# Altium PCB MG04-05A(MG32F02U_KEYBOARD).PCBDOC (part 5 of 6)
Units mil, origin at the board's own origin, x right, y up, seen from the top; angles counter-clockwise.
Board outline 17912.8 x 10422.68 mil, 2 copper layers (Top Layer, Bottom Layer); 623 components, 347 nets, 1816 pads, 821 vias.
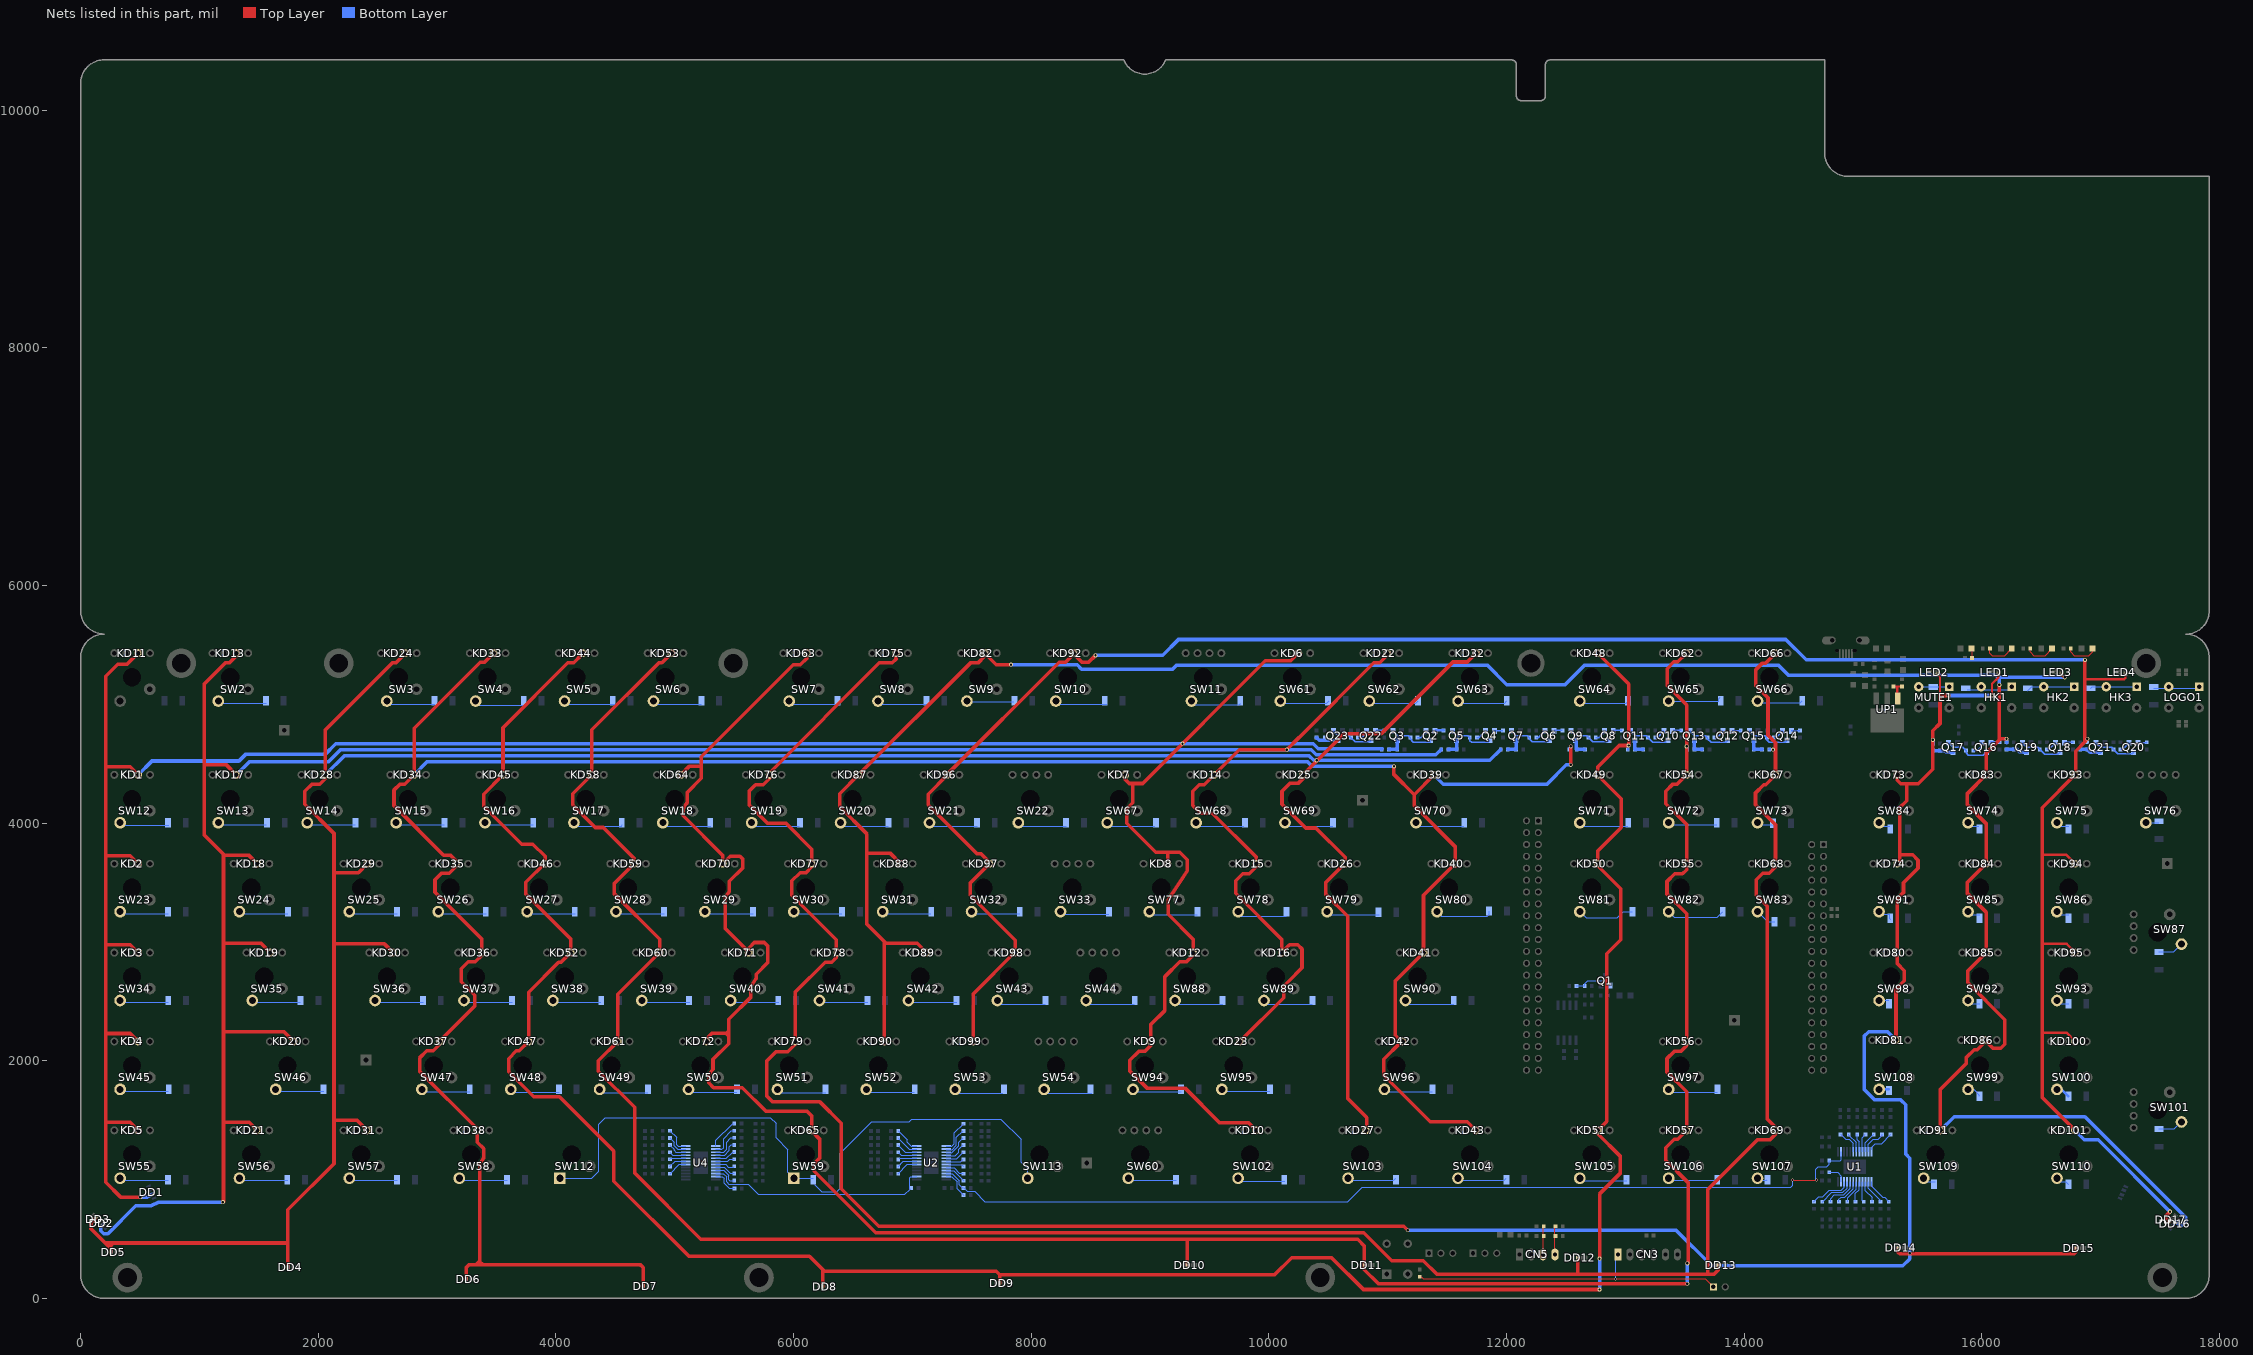
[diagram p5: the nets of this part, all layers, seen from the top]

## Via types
v1: diameter 30, hole 12, Top Layer to Bottom Layer, tented both sides, 273 vias
v2: diameter 26, hole 16, Top Layer to Bottom Layer, tented both sides, 181 vias
v3: diameter 26, hole 12, Top Layer to Bottom Layer, tented both sides, 165 vias
v4: diameter 33, hole 20, Top Layer to Bottom Layer, tented both sides, 61 vias
v5: diameter 25, hole 12, Top Layer to Bottom Layer, tented both sides, 47 vias
v6: diameter 20, hole 12, Top Layer to Bottom Layer, tented both sides, 40 vias
v7: diameter 30, hole 16, Top Layer to Bottom Layer, tented both sides, 30 vias
v8: diameter 28, hole 16, Top Layer to Bottom Layer, tented both sides, 12 vias
v9: diameter 35, hole 20, Top Layer to Bottom Layer, tented both sides, 5 vias
v10: diameter 25, hole 16, Top Layer to Bottom Layer, tented both sides, 3 vias
v11: diameter 40, hole 12, Top Layer to Bottom Layer, tented both sides, 3 vias
v12: diameter 40, hole 20, Top Layer to Bottom Layer, tented both sides, 1 vias

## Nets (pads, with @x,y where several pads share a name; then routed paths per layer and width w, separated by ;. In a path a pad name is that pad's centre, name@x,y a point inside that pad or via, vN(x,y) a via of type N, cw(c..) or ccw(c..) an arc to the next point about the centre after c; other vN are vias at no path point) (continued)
NetD5_1: D5.1 SW2.1 | length 400
  Bottom Layer w8: SW2.1@1163.15,5010 D5.1@1563.15,5010
NetD6_1: D6.1 SW3.1 | length 375.1
  Bottom Layer w8: SW3.1@2603.27,5000 D6.1@2978.35,5000
NetD7_1: D7.1 SW4.1 | length 378.3
  Bottom Layer w8: SW4.1@3350.04,4993.11 D7.1@3728.35,4993.11
NetD8_1: D8.1 SW5.1 | length 400.1
  Bottom Layer w8: SW5.1@4099.27,5000 D8.1@4499.37,5000
NetD9_1: D9.1 SW6.1 | length 375.9
  Bottom Layer w8: SW6.1@4847.27,5000 D9.1@5223.15,5000
NetD10_1: D10.1 SW7.1 | length 400.1
  Bottom Layer w8: SW7.1@5989.28,5000 D10.1@6389.37,5000
NetD11_1: D11.1 SW8.1 | length 400.1
  Bottom Layer w8: SW8.1@6736.94,5000 D11.1@7137.04,5000
NetD12_1: D12.1 SW9.1 | length 393.9
  Bottom Layer w8: SW9.1@7458.13,5020 D12.1@7852,5020
NetD13_1: D13.1 SW10.1 | length 400.1
  Bottom Layer w8: SW10.1@8233.05,5000 D13.1@8633.15,5000
NetD14_1: D14.1 SW11.1 | length 435.2
  Bottom Layer w8: SW11.1@9347.98,5026.89 9359.05,5015.81 9359.05,5007.73 9370.31,4996.47 9749,4996.47 9758.35,5005.81 D14.1@9762,5005.81
NetD15_1: D15.1 SW12.1 | length 403.1
  Bottom Layer w8: SW12.1@336.9,3980 D15.1@740,3980
NetD16_1: D16.1 SW13.1 | length 400
  Bottom Layer w8: SW13.1@1163.74,3986.4 D16.1@1563.74,3986.4
NetD17_1: D17.1 SW14.1 | length 400
  Bottom Layer w8: SW14.1@1911.62,3986.4 D17.1@2311.62,3986.4
NetD18_1: D18.1 SW15.1 | length 400
  Bottom Layer w8: SW15.1@2659.73,3986.4 D18.1@3059.73,3986.4
NetD19_1: D19.1 SW16.1 | length 400
  Bottom Layer w8: SW16.1@3407.73,3986.4 D19.1@3807.73,3986.4
NetD20_1: D20.1 SW17.1 | length 412.6
  Bottom Layer w8: SW17.1@4155.76,3971.4 4553.15,3971.4 D20.1@4555.76,3986.4
NetD21_1: D21.1 SW18.1 | length 397.4
  Bottom Layer w8: SW18.1@4903.75,3971.4 D21.1@5301.14,3971.4
NetD22_1: D22.1 SW19.1 | length 397.4
  Bottom Layer w8: SW19.1@5651.78,3971.4 D22.1@6049.17,3971.4
NetD23_1: D23.1 SW20.1 | length 397.4
  Bottom Layer w8: SW20.1@6399.82,3971.4 D23.1@6797.22,3971.4
NetD24_1: D24.1 SW21.1 | length 397.4
  Bottom Layer w8: SW21.1@7147.9,3971.4 D24.1@7545.29,3971.4
NetD25_1: D25.1 SW22.1 | length 397.4
  Bottom Layer w8: SW22.1@7895.89,3971.4 D25.1@8293.28,3971.4
NetD26_1: D26.1 SW23.1 | length 400
  Bottom Layer w8: SW23.1@336.85,3238 D26.1@736.85,3238
NetD27_1: D27.1 SW24.1 | length 400
  Bottom Layer w8: SW24.1@1340.79,3238 D27.1@1740.79,3238
NetD28_1: D28.1 SW25.1 | length 400
  Bottom Layer w8: SW25.1@2266.18,3238 D28.1@2666.18,3238
NetD29_1: D29.1 SW26.1 | length 400
  Bottom Layer w8: SW26.1@3014.06,3238 D29.1@3414.06,3238
NetD30_1: D30.1 SW27.1 | length 400
  Bottom Layer w8: SW27.1@3762.1,3238 D30.1@4162.1,3238
NetD31_1: D31.1 SW28.1 | length 400
  Bottom Layer w8: SW28.1@4510.09,3238 D31.1@4910.09,3238
NetD32_1: D32.1 SW29.1 | length 400
  Bottom Layer w8: SW29.1@5258.16,3238 D32.1@5658.16,3238
NetD33_1: D33.1 SW30.1 | length 400
  Bottom Layer w8: SW30.1@6006.15,3238 D33.1@6406.15,3238
NetD34_1: D34.1 SW31.1 | length 400
  Bottom Layer w8: SW31.1@6754.22,3238 D34.1@7154.22,3238
NetD35_1: D35.1 SW32.1 | length 400
  Bottom Layer w8: SW32.1@7502.27,3238 D35.1@7902.27,3238
NetD36_1: D36.1 SW33.1 | length 400
  Bottom Layer w8: SW33.1@8250.3,3233 D36.1@8650.3,3233
NetD37_1: D37.1 SW34.1 | length 400
  Bottom Layer w8: SW34.1@336.85,2490.4 D37.1@736.85,2490.4
NetD38_1: D38.1 SW35.1 | length 400
  Bottom Layer w8: SW35.1@1449.06,2490.4 D38.1@1849.06,2490.4
NetD39_1: D39.1 SW36.1 | length 400
  Bottom Layer w8: SW36.1@2482.52,2490.4 D39.1@2882.52,2490.4
NetD40_1: D40.1 SW37.1 | length 400
  Bottom Layer w8: SW37.1@3230.6,2490.4 D40.1@3630.6,2490.4
NetD41_1: D41.1 SW38.1 | length 400
  Bottom Layer w8: SW38.1@3978.63,2490.4 D41.1@4378.63,2490.4
NetD42_1: D42.1 SW39.1 | length 400
  Bottom Layer w8: SW39.1@4726.67,2490.4 D42.1@5126.67,2490.4
NetD43_1: D43.1 SW40.1 | length 400
  Bottom Layer w8: SW40.1@5474.7,2490.4 D43.1@5874.7,2490.4
NetD44_1: D44.1 SW41.1 | length 400
  Bottom Layer w8: SW41.1@6222.73,2490.4 D44.1@6622.73,2490.4
NetD45_1: D45.1 SW42.1 | length 400
  Bottom Layer w8: SW42.1@6970.76,2490.4 D45.1@7370.76,2490.4
NetD46_1: D46.1 SW43.1 | length 400
  Bottom Layer w8: SW43.1@7718.8,2475.4 D46.1@8118.8,2475.4
NetD47_1: D47.1 SW44.1 | length 400
  Bottom Layer w8: SW44.1@8466.79,2475.4 D47.1@8866.79,2475.4
NetD48_1: D48.1 SW45.1 | length 400
  Bottom Layer w8: SW45.1@336.85,1742.3 D48.1@736.85,1742.3
NetD49_1: D49.1 SW46.1 | length 400
  Bottom Layer w8: SW46.1@1645.91,1742.3 D49.1@2045.91,1742.3
NetD50_1: D50.1 SW47.1 | length 398
  Bottom Layer w8: SW47.1@2876.23,1737.3 D50.1@3274.28,1737.3
NetD51_1: D51.1 SW48.1 | length 400
  Bottom Layer w8: SW48.1@3627.02,1735 D51.1@4027,1735
NetD52_1: D52.1 SW49.1 | length 400
  Bottom Layer w8: SW49.1@4372,1730 D52.1@4772,1730
NetD53_1: D53.1 SW50.1 | length 400
  Bottom Layer w8: SW50.1@5122,1735 D53.1@5522,1735
NetD54_1: D54.1 SW51.1 | length 400
  Bottom Layer w8: SW51.1@5868.37,1732.3 D54.1@6268.37,1732.3
NetD55_1: D55.1 SW52.1 | length 400
  Bottom Layer w8: SW52.1@6617,1735 D55.1@7017,1735
NetD56_1: D56.1 SW53.1 | length 400
  Bottom Layer w8: SW53.1@7359.44,1727.3 D56.1@7759.44,1727.3
NetD57_1: D57.1 SW54.1 | length 396.6
  Bottom Layer w8: SW54.1@8112.48,1727.3 D57.1@8509.08,1727.3
NetD58_1: D58.1 SW55.1 | length 400
  Bottom Layer w8: SW55.1@336.85,994.3 D58.1@736.85,994.3
NetD59_1: D59.1 SW56.1 | length 400
  Bottom Layer w8: SW56.1@1340.8,994.3 D59.1@1740.8,994.3
NetD60_1: D60.1 SW57.1 | length 400
  Bottom Layer w8: SW57.1@2266,994.3 D60.1@2666,994.3
NetD61_1: D61.1 SW58.1 | length 400
  Bottom Layer w8: SW58.1@3191.21,994.3 D61.1@3591.21,994.3
NetD62_1: D62.1 SW59.1 SW112.1 SW113.1 | length 5585.9
  Bottom Layer w8: SW112.1@4032.9,1011.19 4302.34,1011.19 4361.85,1070.7 4361.85,1465.7 4416.68,1520.53 5804.89,1520.53 5852.69,1472.72 5852.69,1350.77 5952,1251.47 5952,1060.6 SW59.1@6001.41,1011.19 D62.1@6164.63,1011.19 ; D62.1@6171.85,960.7 6236.85,895.7 6361.23,895.7 6393.21,927.68 6393.21,1222.06 6656.41,1485.25 6971.41,1485.25 6995.64,1509.48 7743.98,1509.48 7915.64,1337.83 7915.64,1147.83 7969.91,1093.55 SW113.1@7969.91,1011.19
NetD63_1: D63.1 SW60.1 | length 400
  Bottom Layer w8: SW60.1@8821.14,994.3 D63.1@9221.14,994.3
NetD64_1: D64.1 SW61.1 | length 425.6
  Bottom Layer w8: SW61.1@10095.89,5026.89 10112.78,5010 10486.26,5010 D64.1@10506.26,5030
NetD65_1: D65.1 SW62.1 | length 425.6
  Bottom Layer w8: SW62.1@10844.08,5026.89 10860.97,5010 11234.45,5010 D65.1@11254.45,5030
NetD66_1: D66.1 SW63.1 | length 425.6
  Bottom Layer w8: SW63.1@11592,5026.89 11608.89,5010 11982.37,5010 D66.1@12002.37,5030
NetD67_1: D67.1 SW64.1 | length 425.6
  Bottom Layer w8: SW64.1@12615.74,5026.89 12632.62,5010 13006.11,5010 D67.1@13026.11,5030
NetD68_1: D68.1 SW65.1 | length 460.2
  Bottom Layer w8: SW65.1@13363.65,5026.89 13785.35,5026.89 13785.35,5047 D68.1@13798.35,5060
NetD69_1: D69.1 SW66.1 | length 383.1
  Bottom Layer w8: SW66.1@14113.15,5011 14469.35,5011 D69.1@14488.35,5030
NetD70_1: D70.1 HK1.1 HK1.3 | length 378.6
  Bottom Layer w8: D70.1@15875.41,5123.48 HK1.3@15994,5123.48 ; HK1.3@15993.6,5123.48 HK1.3@15994,5123.48 ; HK1.1@16249.6,5123.48 HK1.3@15994,5123.48 ; HK1.1@16250,5147 HK1.1@16254,5147
NetD71_1: D71.1 HK2.1 HK2.3 | length 402.3
  Bottom Layer w8: D71.1@16387,5114.8 16419.2,5147 HK2.3@16520,5147 HK2.1@16776,5147
NetD72_1: D72.1 HK3.1 HK3.3 | length 390.1
  Bottom Layer w8: D72.1@16917,5134.8 16929.2,5147 HK3.3@17046,5147 HK3.1@17302,5147
NetD73_1: D73.1 SW67.1 | length 400
  Bottom Layer w8: SW67.1@8638.15,3975 D73.1@9038.15,3975
NetD74_1: D74.1 SW68.1 | length 397.4
  Bottom Layer w8: SW68.1@9392.03,3971.4 D74.1@9789.42,3971.4
NetD75_1: D75.1 SW69.1 | length 397.4
  Bottom Layer w8: SW69.1@10140.02,3971.4 D75.1@10537.42,3971.4
NetD76_1: D76.1 SW70.1 | length 397.4
  Bottom Layer w8: SW70.1@11242.47,3971.4 D76.1@11639.86,3971.4
NetD77_1: D77.1 SW71.1 | length 397.4
  Bottom Layer w8: SW71.1@12620.35,3971.4 D77.1@13017.74,3971.4
NetD78_1: D78.1 SW72.1 | length 400
  Bottom Layer w8: SW72.1@13368.42,3986.4 D78.1@13768.42,3986.4
NetD79_1: D79.1 SW73.1 | length 125.7
  Bottom Layer w8: SW73.1@14116.45,3986.4 D79.1@14242.2,3986.4
NetD80_1: D80.1 MUTE1.1 MUTE1.3 | length 256
  Bottom Layer w8: MUTE1.3@15468,5147 MUTE1.1@15724,5147
NetD81_1: D81.1 SW74.1 | length 101.3
  Bottom Layer w8: SW74.1@15883.52,4003.29 15911.81,3975 D81.1@15973.15,3975
NetD82_1: D82.1 SW75.1 | length 98.7
  Bottom Layer w8: SW75.1@16631.35,3975 D82.1@16730.09,3975
NetD83_1: D83.1 SW76.1 | length 98.7
  Bottom Layer w8: SW76.1@17389.6,4001.25 D83.1@17488.34,4001.25
NetD84_1: D84.1 SW77.1 | length 400
  Bottom Layer w8: SW77.1@8998.33,3228 D84.1@9398.33,3228
NetD85_1: D85.1 SW78.1 | length 400
  Bottom Layer w8: SW78.1@9746.36,3218 D85.1@10146.36,3218
NetD86_1: D86.1 SW79.1 | length 437.6
  Bottom Layer w8: SW79.1@10489.39,3228 D86.1@10927,3228
NetD87_1: D87.1 SW80.1 | length 486.7
  Bottom Layer w8: SW80.1@11414.79,3254.89 11451.68,3218 11838.53,3218 11852.2,3231.66 D87.1@11852.2,3260
NetD88_1: D88.1 SW81.1 | length 486.6
  Bottom Layer w8: SW81.1@12615.58,3254.89 12668.47,3202 12929.15,3202 12982.04,3254.89 D88.1@13058.35,3254.89
NetD89_1: D89.1 SW82.1 | length 492.7
  Bottom Layer w8: SW82.1@13363.65,3254.89 13409.54,3209 13772.46,3209 D89.1@13818.35,3254.89
NetD90_1: D90.1 SW83.1 | length 178.8
  Bottom Layer w8: SW83.1@14111.65,3254.89 14196.65,3169.89 D90.1@14255.2,3169.89
NetD91_1: D91.1 SW84.1 | length 67.9
  Bottom Layer w8: SW84.1@15155.26,3975 D91.1@15223.15,3975
NetD92_1: D92.1 SW85.1 | length 98.7
  Bottom Layer w8: SW85.1@15883.34,3226.6 D92.1@15982.09,3226.6
NetD93_1: D93.1 SW86.1 | length 98.7
  Bottom Layer w8: SW86.1@16630.57,3226.6 D93.1@16729.31,3226.6
NetD94_1: D94.1 SW87.1 | length 217
  Bottom Layer w8: D94.1@17489.6,2916.05 17614.4,2916.05 SW87.1@17679.6,2981.25
NetD95_1: D95.1 SW88.1 | length 395.6
  Bottom Layer w8: SW88.1@9214.87,2475.4 D95.1@9610.43,2475.4
NetD96_1: D96.1 SW89.1 | length 400
  Bottom Layer w8: SW89.1@9962.9,2475.4 D96.1@10362.9,2475.4
NetD97_1: D97.1 SW90.1 | length 400
  Bottom Layer w8: SW90.1@11153.85,2475.4 D97.1@11553.85,2475.4
NetD98_1: D98.1 SW91.1 | length 155
  Bottom Layer w8: SW91.1@15123.24,3260.95 15151.38,3232.8 15224.28,3232.8 15224.28,3195.94 D98.1@15228.09,3192.13
NetD99_1: D99.1 SW92.1 | length 98.7
  Bottom Layer w8: SW92.1@15883.52,2479 D99.1@15982.27,2479
NetD100_1: D100.1 SW93.1 | length 98.7
  Bottom Layer w8: SW93.1@16631.57,2479 D100.1@16730.31,2479
NetD101_1: D101.1 SW94.1 | length 403.3
  Bottom Layer w8: SW94.1@8859.08,1737.29 D101.1@9262.42,1737.29
NetD102_1: D102.1 SW95.1 | length 400
  Bottom Layer w8: SW95.1@9608.54,1742.3 D102.1@10008.54,1742.3
NetD103_1: D103.1 SW96.1 | length 412.2
  Bottom Layer w8: SW96.1@10971.89,1759.19 10993.34,1737.74 D103.1@11375.23,1737.74
NetD104_1: D104.1 SW97.1 | length 414.6
  Bottom Layer w8: SW97.1@13362.5,1740 13363.65,1735 D104.1@13773.15,1735
NetD105_1: D105.1 SW98.1 | length 81.9
  Bottom Layer w8: SW98.1@15134.84,2507.29 D105.1@15216.77,2507.29
NetD106_1: D106.1 SW99.1 | length 125.3
  Bottom Layer w8: SW99.1@15883.5,1759.19 15929.28,1759.19 15978.35,1710.12 D106.1@15978.35,1700
NetD107_1: D107.1 SW100.1 | length 121.5
  Bottom Layer w20: SW100.1@16631.36,1759.19 16669.16,1759.19 D107.1@16728.35,1700
NetD108_1: D108.1 SW101.1 | length 214.4
  Bottom Layer w8: D108.1@17489.6,1426.05 17620.46,1426.05 SW101.1@17679.5,1485.09
NetD109_1: D109.1 SW102.1 | length 372
  Bottom Layer w8: SW102.1@9759.15,986 D109.1@10131.15,986
NetD110_1: D110.1 SW103.1 | length 404.8
  Bottom Layer w8: SW103.1@10670.54,994.3 11051.45,994.3 D110.1@11068.35,1011.2
NetD111_1: D111.1 SW104.1 | length 421.4
  Bottom Layer w8: SW104.1@11590.98,1011.19 11607.87,994.3 11981.45,994.3 D111.1@11998.35,1011.2
NetD112_1: D112.1 SW105.1 | length 392.8
  Bottom Layer w8: SW105.1@12617,990 D112.1@13009.75,990
NetD113_1: D113.1 SW106.1 | length 423.5
  Bottom Layer w8: SW106.1@13363.65,1011.19 13380.54,994.3 13756.25,994.3 D113.1@13773.15,1011.2
NetD114_1: D114.1 SW107.1 | length 81.1
  Bottom Layer w8: SW107.1@14116.43,994.3 14189.61,994.3 D114.1@14195.2,999.89
NetD115_1: D115.1 SW108.1 | length 82.9
  Bottom Layer w20: SW108.1@15135.47,1759.19 D115.1@15218.35,1759.19
NetD116_1: D116.1 SW109.1 | length 98.7
  Bottom Layer w8: SW109.1@15509.49,982.9 D116.1@15608.24,982.9
NetD117_1: D117.1 SW110.1 | length 106.3
  Bottom Layer w8: SW110.1@16631.54,982.9 16705.45,982.9 D117.1@16728.35,960
NetD118_1: D118.1 LOGO1.1 LOGO1.3 | length 368.8
  Bottom Layer w8: D118.1@17447,5134.8 LOGO1.1@17815.8,5134.8
NetD119_2: D119.2 R90.1 | length 91
  Top Layer w8: D119.2@15911,5460 D119.2@15917,5454 ; D119.2@15911,5470 15917,5464 D119.2@15917,5454 ; R90.1@15917,5390 D119.2@15917,5454
NetD120_2: D120.2 R99.1 | length 257.1
  Top Layer w10: R99.1@16067,5470 16067,5430 16087,5410 16191,5410 D120.2@16251,5470
NetD121_2: D121.2 R107.1 | length 251.3
  Top Layer w8: R107.1@16407,5470 16407,5440 16437,5410 16531,5410 D121.2@16591,5470
NetD122_2: D122.2 R108.1 | length 268.9
  Top Layer w8: R108.1@16747,5470 16747,5440 16777,5410 16901,5410 16931,5440 D122.2@16931,5470
NetQ1_1: Q1.1 R2.2 R3.1 | length 329.1
  Bottom Layer w8: R2.2@12587,2630 R3.1@12657,2630 12657,2649.59 12681.41,2674 12828.4,2674 Q1.1@12869.4,2633
NetQ2_1: Q2.1 R6.2 | length 91.7
  Bottom Layer w12: R6.2@11250,4720 11276.6,4720 Q2.1@11322.6,4766
NetQ2_2: Q2.2 R8.2 | length 68.6
  Bottom Layer w20: Q2.2@11401.4,4780 R8.2@11470,4780
NetQ2_3: Q2.3 Q3.1 R7.2 | length 363.4
  Bottom Layer w12: Q3.1@11042.6,4776 11082.1,4736.5 11173.5,4736.5 R7.2@11190,4720 11190,4708 11216,4682 Q2.3@11360,4682
NetQ3_3: Q3.3 R9.2 R10.1 | length 147.3
  Bottom Layer w30: R10.1@11010,4620 R9.2@11080,4620 Q3.3@11080,4697.26
NetQ4_1: Q4.1 R11.2 | length 95.8
  Bottom Layer w12: R11.2@11750,4720 11766.6,4720 Q4.1@11822.6,4776
NetQ4_2: Q4.2 R13.2 | length 68.6
  Bottom Layer w12: Q4.2@11897.4,4776 R13.2@11966,4776
NetQ4_3: Q4.3 Q5.1 R12.2 | length 379
  Bottom Layer w12: Q5.1@11542.6,4776 11582.1,4736.5 11673.5,4736.5 R12.2@11690,4720 11690,4695 11705,4680 11842.74,4680 Q4.3@11860,4697.26
NetQ5_3: Q5.3 R14.2 R15.1 | length 147.3
  Bottom Layer w30: R15.1@11510,4620 R14.2@11580,4620 Q5.3@11580,4697.26
NetQ6_1: Q6.1 R16.2 | length 95.8
  Bottom Layer w12: R16.2@12250,4720 12266.6,4720 Q6.1@12322.6,4776
NetQ6_2: Q6.2 R18.2 | length 68.6
  Bottom Layer w12: Q6.2@12401.4,4780 R18.2@12470,4780
NetQ6_3: Q6.3 Q7.1 R17.2 | length 366
  Bottom Layer w12: Q7.1@12042.6,4776 12082.1,4736.5 12173.5,4736.5 R17.2@12190,4720 12190,4710 12215,4685 12347.74,4685 Q6.3@12360,4697.26
NetQ7_3: Q7.3 R19.2 R20.1 | length 147.3
  Bottom Layer w30: R20.1@12010,4620 R19.2@12080,4620 Q7.3@12080,4697.26
NetQ8_1: Q8.1 R21.2 | length 101.7
  Bottom Layer w12: R21.2@12750,4720 12776.6,4720 12822.6,4766 Q8.1@12822.6,4776
NetQ8_2: Q8.2 R23.2 | length 72.6
  Bottom Layer w12: Q8.2@12897.4,4780 R23.2@12970,4780
NetQ8_3: Q8.3 Q9.1 R22.2 | length 360.2
  Bottom Layer w12: Q9.1@12542.6,4776 12582.1,4736.5 12673.5,4736.5 R22.2@12690,4720 12725,4685 12847.74,4685 Q8.3@12860,4697.26
NetQ9_3: Q9.3 R24.2 R25.1 | length 137.2
  Bottom Layer w30: R25.1@12587,4621.4 Q9.3@12587,4690 ; R25.1@12590,4620 R24.2@12658.6,4620
NetQ10_1: Q10.1 R26.2 | length 95.8
  Bottom Layer w12: R26.2@13250,4720 13266.6,4720 Q10.1@13322.6,4776
NetQ10_2: Q10.2 R28.2 | length 68.6
  Bottom Layer w12: Q10.2@13401.4,4780 R28.2@13470,4780
NetQ10_3: Q10.3 Q11.1 R27.2 | length 364.9
  Bottom Layer w12: Q11.1@13042.6,4776 13082.1,4736.5 13173.5,4736.5 R27.2@13190,4720 13230,4680 13240,4680 ; 13265,4680 13240,4680 ; Q10.3@13342.74,4680 13240,4680
NetQ11_3: Q11.3 R29.2 R30.1 | length 147.3
  Bottom Layer w30: Q11.3@13080,4697.26 R30.1@13080,4620 R29.2@13150,4620
NetQ12_1: Q12.1 R31.2 | length 95.8
  Bottom Layer w12: R31.2@13750,4720 13766.6,4720 Q12.1@13822.6,4776
NetQ12_2: Q12.2 R33.2 | length 74.3
  Bottom Layer w12: Q12.2@13897.4,4776 13966,4776 R33.2@13970,4780
NetQ12_3: Q12.3 Q13.1 R32.2 | length 373.3
  Bottom Layer w12: Q13.1@13542.6,4776 13582.1,4736.5 13673.5,4736.5 R32.2@13690,4720 13690,4710 13720,4680 13845.87,4680 13861.56,4695.7 Q12.3@13860,4697.26
NetQ13_3: Q13.3 R34.2 R35.1 | length 145.9
  Bottom Layer w12: R34.2@13646.6,4620 R34.2@13648.6,4620
  Bottom Layer w30: Q13.3@13580,4697.26 R35.1@13580,4620 R34.2@13646.6,4620
NetQ14_1: Q14.1 R36.2 | length 95.8
  Bottom Layer w12: R36.2@14250,4720 14266.6,4720 Q14.1@14322.6,4776
NetQ14_2: Q14.2 R38.2 | length 68.6
  Bottom Layer w12: Q14.2@14397.4,4776 R38.2@14466,4776
NetQ14_3: Q14.3 Q15.1 R37.2 | length 376
  Bottom Layer w12: Q15.1@14042.6,4776 14082.1,4736.5 14173.5,4736.5 R37.2@14190,4720 14190,4700 14210,4680 14342.74,4680 Q14.3@14360,4697.26
NetQ15_3: Q15.3 R39.2 R40.1 | length 147.3
  Bottom Layer w30: Q15.3@14080,4697.26 R39.2@14080,4620 R40.1@14150,4620
NetQ16_1: Q16.1 R41.2 | length 116
  Bottom Layer w12: R41.2@15927,4610 15961,4610 15989,4638 15989,4665.4 Q16.1@15999.6,4676
NetQ16_2: Q16.2 R43.2 | length 68.6
  Bottom Layer w20: Q16.2@16078.4,4680 R43.2@16147,4680
NetQ16_3: Q16.3 Q17.1 R42.2 | length 382.1
  Bottom Layer w12: Q17.1@15719.6,4676 15759.1,4636.5 15840.5,4636.5 R42.2@15867,4610 15867,4591 15886,4572 16011.74,4572 Q16.3@16037,4597.26
NetQ17_3: Q17.3 R44.2 R45.1 | length 175.3
  Bottom Layer w30: R45.1@15587,4610 15687.55,4610 15700.29,4597.26 Q17.3@15757,4597.26
NetQ18_1: Q18.1 R46.2 | length 95.8
  Bottom Layer w12: R46.2@16547,4620 16563.6,4620 Q18.1@16619.6,4676
NetQ18_2: Q18.2 R48.2 | length 74.3
  Bottom Layer w12: Q18.2@16694.4,4676 16698.4,4680 R48.2@16767,4680
NetQ18_3: Q18.3 Q19.1 R47.2 | length 364.3
  Bottom Layer w12: Q19.1@16339.6,4676 16379.1,4636.5 16470.5,4636.5 R47.2@16487,4620 16527,4580 16639.74,4580 Q18.3@16657,4597.26
NetQ19_3: Q19.3 R49.2 R50.1 | length 179.4
  Bottom Layer w30: R50.1@16207,4620 R49.2@16267,4620 16297.55,4620 16320.29,4597.26 Q19.3@16377,4597.26
NetQ20_1: Q20.1 R51.2 | length 95.8
  Bottom Layer w12: R51.2@17167,4620 17183.6,4620 Q20.1@17239.6,4676
NetQ20_2: Q20.2 R53.2 | length 74.3
  Bottom Layer w12: Q20.2@17314.4,4676 17383,4676 R53.2@17387,4680
NetQ20_3: Q20.3 Q21.1 R52.2 | length 360.2
  Bottom Layer w12: Q21.1@16959.6,4676 16999.1,4636.5 17090.5,4636.5 R52.2@17107,4620 17142,4585 17264.74,4585 Q20.3@17277,4597.26
NetQ21_3: Q21.3 R54.2 R55.1 | length 179.4
  Bottom Layer w30: R54.2@16827,4620 R55.1@16887,4620 16909.74,4597.26 Q21.3@16997,4597.26
NetQ22_1: Q22.1 R56.2 | length 107
  Bottom Layer w8: Q22.1@10822.6,4762.6 Q22.1@10822.6,4776
  Bottom Layer w12: R56.2@10750,4720 10780,4720 10822.6,4762.6 Q22.1@10822.6,4766
NetQ22_2: Q22.2 R58.2 | length 68.6
  Bottom Layer w12: Q22.2@10901.4,4780 R58.2@10970,4780
NetQ22_3: Q22.3 Q23.1 R57.2 | length 359.9
  Bottom Layer w12: Q23.1@10543.1,4776.5 10582.6,4737 10673,4737 R57.2@10690,4720 10725,4685 10847.74,4685 Q22.3@10860,4697.26
NetQ23_3: Q23.3 R59.2 R60.1 | length 189.4
  Bottom Layer w30: R60.1@10400,4720 10422.74,4697.26 Q23.3@10580,4697.26
NetR4_2: R4.2 R5.1 UP1.1 | length 172
  Top Layer w20: R4.2@15257,5150 15288,5150 ; UP1.1@15288,5048 15288,5150 ; R5.1@15327,5150 15288,5150
NetR64_1: R64.1 U1.23 | length 164.3
  Bottom Layer w8: R64.1@14710,1059.89 14785,1059.89 14814.84,1030.04 U1.23@14814.84,982.92
NetR65_1: R65.1 U1.21 | length 311.9
  Bottom Layer w8: R65.1@14656,813.89 14659.42,813.89 14737,891.47 14829.01,891.47 14866.02,928.48 U1.21@14866.02,982.92
NetR66_1: R66.1 U1.20 | length 298.4
  Bottom Layer w8: R66.1@14726,813.89 14726,840.47 14757,871.47 14837.81,871.47 14891.61,925.27 14891.61,939.89 ; 14891.61,926.5 14891.61,939.89 ; U1.20@14891.61,982.92 14891.61,939.89
NetR67_2: R67.2 U1.6 | length 208.2
  Bottom Layer w8: R67.2@14810,1379.89 14812.11,1379.89 14852,1340 14882,1340 14917.21,1304.8 U1.6@14917.21,1234.89
NetR68_1: R68.1 U1.19 | length 238
  Bottom Layer w8: R68.1@14796,813.89 14796,833.46 14814.01,851.47 14846.09,851.47 14917.21,922.58 U1.19@14917.21,982.92
NetR69_2: R69.2 U1.7 | length 171
  Bottom Layer w8: R69.2@14880,1379.89 14880,1374.89 14942.8,1312.09 U1.7@14942.8,1234.89
NetR70_1: R70.1 U1.18 | length 198.8
  Bottom Layer w8: R70.1@14871,813.89 14871,848.09 14942.8,919.89 U1.18@14942.8,982.92
NetR71_2: R71.2 U1.8 | length 152.6
  Bottom Layer w8: R71.2@14950,1379.89 14950,1334.89 14968.39,1316.5 U1.8@14968.39,1234.89
NetR72_1: R72.1 U1.17 | length 182.4
  Bottom Layer w8: R72.1@14936,813.89 14936,883.46 14968.39,915.84 U1.17@14968.39,982.92
NetR73_2: R73.2 U1.9 | length 156.1
  Bottom Layer w8: U1.9@14993.15,1234.89 14993.15,1353.04 R73.2@15020,1379.89
NetR74_1: R74.1 U1.16 | length 163
  Bottom Layer w8: R74.1@14993.98,819.89 U1.16@14993.98,982.92
NetR75_2: R75.2 U1.10 | length 174.2
  Bottom Layer w8: U1.10@15019.57,1234.89 15019.57,1309.57 15089.89,1379.89 R75.2@15090,1379.89
NetR76_1: R76.1 U1.15 | length 192.4
  Bottom Layer w8: U1.15@15019.57,982.92 15019.57,907.58 15076,851.15 R76.1@15076,813.89
NetR77_2: R77.2 U1.11 | length 216
  Bottom Layer w8: U1.11@15045.16,1234.89 15045.16,1298.16 15087,1340 15127,1340 15160,1373 R77.2@15160,1379.89
NetR78_1: R78.1 U1.14 | length 210.8
  Bottom Layer w8: U1.14@15045.16,982.92 15045.16,926.99 15146,826.15 R78.1@15146,813.89
NetR79_2: R79.2 U1.12 | length 224.4
  Bottom Layer w8: U1.12@15070,1254.89 15070.75,1254.89 15070.75,1270.94 15103.29,1303.48 15156.63,1303.48 R79.2@15233.15,1380
NetR80_1: R80.1 U1.13 | length 237.8
  Bottom Layer w8: U1.13@15070.75,982.92 15070.75,944.4 15165.35,849.8 15180.08,849.8 R80.1@15216,813.89
NetR83_1: R83.1 U2.23 | length 239.5
  Bottom Layer w8: U2.23@7285.98,1022.52 7332.36,1022.52 7375,979.89 7375,924.89 R83.1@7430,869.89
NetR85_1: R85.1 U2.21 | length 178.7
  Bottom Layer w8: U2.21@7285.98,1073.71 7346.18,1073.71 R85.1@7430,989.89
NetR87_1: R87.1 U2.20 | length 164.5
  Bottom Layer w8: U2.20@7285.98,1099.3 7350.59,1099.3 7395,1054.89 7425,1054.89 R87.1@7430,1049.89
NetR88_2: R88.2 U2.6 | length 186.3
  Bottom Layer w8: R88.2@6880,1049.89 6957.95,1127.84 U2.6@7034.02,1127.84
NetR89_1: R89.1 U2.19 | length 126.8
  Bottom Layer w8: U2.19@7305,1124.89 7412.68,1124.89 R89.1@7426.17,1111.39
NetR91_2: R91.2 U2.7 | length 172.1
  Bottom Layer w8: R91.2@6880,1109.89 6923.54,1153.43 U2.7@7034.02,1153.43
NetR92_1: R92.1 U2.18 | length 148.9
  Bottom Layer w8: U2.18@7285.98,1150.48 7405.26,1150.48 R92.1@7426.17,1171.39
NetR93_2: R93.2 U2.8 | length 144.9
  Bottom Layer w8: R93.2@6889.13,1179.02 U2.8@7034.02,1179.02
NetR94_1: R94.1 U2.17 | length 163.1
  Bottom Layer w8: U2.17@7285.98,1176.07 7370.85,1176.07 R94.1@7426.17,1231.39
NetR95_2: R95.2 U2.9 | length 164.5
  Bottom Layer w8: R95.2@6880,1229.89 6905.28,1204.61 U2.9@7034.02,1204.61
NetR96_1: R96.1 U2.16 | length 192.2
  Bottom Layer w8: U2.16@7285.98,1201.66 7361.77,1201.66 7390,1229.89 7390,1255.22 R96.1@7426.17,1291.39
NetR97_2: R97.2 U2.10 | length 178.7
  Bottom Layer w8: R97.2@6880,1289.89 6939.69,1230.2 U2.10@7034.02,1230.2
NetR98_1: R98.1 U2.15 | length 209.4
  Bottom Layer w8: U2.15@7285.98,1227.25 7332.36,1227.25 7390,1284.89 7390,1315.22 R98.1@7426.17,1351.39
NetR103_2: R103.2 U2.11 | length 193
  Bottom Layer w8: R103.2@6880,1349.89 6974.09,1255.79 U2.11@7034.02,1255.79
NetR104_1: R104.1 U2.14 | length 244.1
  Bottom Layer w8: U2.14@7285.98,1252.84 7332.95,1252.84 7370,1289.89 7370,1355.22 R104.1@7426.17,1411.39
NetR105_2: R105.2 U2.12 | length 219
  Bottom Layer w8: R105.2@6880,1409.89 6955,1334.89 6955,1314.89 6988.5,1281.38 U2.12@7034.02,1281.38
NetR106_1: R106.1 U2.13 | length 274.8
  Bottom Layer w8: U2.13@7285.98,1281.38 7331.5,1281.38 7352.32,1302.21 7352.32,1392.21 R106.1@7430,1469.89
NetR110_1: R110.1 U4.23 | length 222.2
  Bottom Layer w8: U4.23@5345.98,1025.48 5399.41,1025.48 5415,1009.89 5415,969.89 5459.89,925 R110.1@5503.15,925
NetR111_1: R111.1 U4.21 | length 210.4
  Bottom Layer w8: U4.21@5345.98,1076.66 5413.23,1076.66 5455,1034.89 5455,999.89 5463.5,991.39 R111.1@5500.58,991.39
NetR112_1: R112.1 U4.20 | length 175.7
  Bottom Layer w8: U4.20@5345.98,1102.25 5417.64,1102.25 5468.5,1051.39 R112.1@5500.58,1051.39
NetR113_2: R113.2 U4.6 | length 166.3
  Bottom Layer w8: R113.2@4960,1049.89 5037.95,1127.84 U4.6@5094.02,1127.84
NetR114_1: R114.1 U4.19 | length 166.8
  Bottom Layer w8: U4.19@5345.98,1127.84 5427.05,1127.84 5450,1104.89 5494.08,1104.89 R114.1@5500.58,1111.39
NetR115_2: R115.2 U4.7 | length 152.9
  Bottom Layer w8: R115.2@4959,1110.31 5002.12,1153.43 U4.7@5094.02,1153.43
NetR116_1: R116.1 U4.18 | length 162
  Bottom Layer w8: U4.18@5345.98,1153.43 5443.54,1153.43 5461.5,1171.39 R116.1@5500.58,1171.39
NetR117_2: R117.2 U4.8 | length 138.6
  Bottom Layer w8: R117.2@4959,1170.31 4967.71,1179.02 U4.8@5094.02,1179.02
NetR118_1: R118.1 U4.17 | length 176.3
  Bottom Layer w8: U4.17@5345.98,1179.02 5434.13,1179.02 5486.5,1231.39 R118.1@5500.58,1231.39
NetR119_2: R119.2 U4.9 | length 145.7
  Bottom Layer w8: R119.2@4959,1230.31 4984.7,1204.61 U4.9@5094.02,1204.61
NetR120_1: R120.1 U4.16 | length 208.1
  Bottom Layer w8: U4.16@5345.98,1204.61 5419.61,1204.61 5460,1245 5460,1274.89 5476.5,1291.39 R120.1@5500.58,1291.39
NetR121_2: R121.2 U4.10 | length 165.4
  Bottom Layer w8: R121.2@4959,1290.31 4995,1254.31 4995,1244.89 5009.69,1230.2 U4.10@5094.02,1230.2
NetR122_1: R122.1 U4.15 | length 239.9
  Bottom Layer w8: U4.15@5345.98,1230.2 5410.2,1230.2 5435,1255 5435,1314.89 5471.5,1351.39 R122.1@5500.58,1351.39
NetR123_2: R123.2 U4.11 | length 191.4
  Bottom Layer w8: R123.2@4959,1350.31 4995,1314.31 4995,1284.89 5024.09,1255.79 U4.11@5094.02,1255.79
NetR124_1: R124.1 U4.14 | length 263
  Bottom Layer w8: U4.14@5345.98,1255.79 5395.91,1255.79 5410,1269.89 5410,1344.89 5476.5,1411.39 R124.1@5500.58,1411.39
NetR125_2: R125.2 U4.12 | length 223.2
  Bottom Layer w8: R125.2@4959,1410.31 5015,1354.31 5015,1295 5028.62,1281.38 U4.12@5094.02,1281.38
NetR126_1: R126.1 U4.13 | length 262.3
  Bottom Layer w8: U4.13@5345.98,1281.38 5345.98,1330.87 5486.5,1471.39 R126.1@5500.58,1471.39
SDO_0: R82.2 U2.2 U4.22 | length 1911.9
  Bottom Layer w8: U4.22@5345.98,1051.07 5408.82,1051.07 5435,1024.89 5435,979.89 5455,959.89 5620,959.89 5704.19,875.7 6935.81,875.7 6980,919.89 6975,924.89 6975,1015 6985.48,1025.48 U2.2@7034.02,1025.48
SDO_1: R63.2 R81.2 U1.2 U2.22 | length 7972.8
  Top Layer w8: v2(14407,996.47) v2(14607,996.47)
  Bottom Layer w8: U2.22@7285.98,1048.12 7336.77,1048.12 7395,989.89 7395,954.89 7420,929.89 R81.2@7430,929.89 7460,899.89 7523.2,899.89 7609.6,813.48 10664.64,813.48 10786.15,935 14390.53,935 14407,951.47 v2(14407,996.47) ; v2@14600,996.47 14600,1085.74 14622.74,1108.48 14694.6,1108.48 14714.64,1128.52 R63.2@14714.64,1159.9 14806.02,1159.9 14814.84,1168.73 U1.2@14814.84,1234.89 U1.2@14814.84,1225.98
SDO_2: R130.2 U1.22 | length 352.6
  Bottom Layer w8: R130.2@14586,813.89 14628.58,856.47 14662,856.47 14717,911.47 14817,911.47 14840.43,934.9 U1.22@14840.43,982.92
SWSRST: CN3.1 JP1.1 R127.1 | length 2720
  Top Layer w10: R127.1@11269.13,182.92 11280.16,182.92 11298.08,165 v2(12917,165) 13671.67,165 JP1.1@13739.76,96.91
  Bottom Layer w8: v2@12917,164.53 v2(12917,165) 12917,350 CN3.1@12937,370
U5V0_RXD: C61.1 CN5.3 R128.1 | length 238.5
  Top Layer w8: CN5.3@12307,370 12307,601.47 R128.1@12312,606.47
U5V0_TXD: C60.1 CN5.4 R129.1 | length 228.5
  Top Layer w8: CN5.4@12407,370 R129.1@12407,598.48
V_1: DD1.1 KD1.1 KD2.1 KD3.1 KD4.1 KD5.1 KD6.1 KD7.1 KD8.1 KD9.1 KD10.1 KD11.1 KD12.1 R10.2 | length 23668.3
  Top Layer w30: KD5.1@483.27,1414.1 415.9,1481.47 212,1481.47 ; KD4.1@483.27,2162.1 415.9,2229.47 212,2229.47 ; KD3.1@483.27,2910.2 415.9,2977.57 212,2977.57 ; KD2.1@483.27,3657.8 415.9,3725.17 212,3725.17 ; KD1.1@483.27,4406.2 415.9,4473.57 212,4473.57 ; KD11.1@483.27,5429.8 389.93,5336.47 312,5336.47 212,5236.47 212,4473.57 ; v4(501.85,852.8) 335.66,852.8 212,976.47 212,1481.47 ; KD7.1@8790.38,4402.2 8790.38,4366.17 8823.15,4333.4 8853.15,4333.4 ; KD8.1@9148.15,3657.8 9148.15,3755 ; KD10.1@9891.76,1414.1 9825.86,1480 9583,1480 9293,1770 8973.08,1770 8829.6,1913.48 8829.6,2003.48 8904.6,2078.48 8954.6,2078.48 9006.93,2130.81 KD9.1@9006.93,2162.1 9006.93,2305.81 9124.6,2423.48 9124.6,2708.48 9249.6,2833.48 9306.29,2833.48 9361.29,2888.48 KD12.1@9361.29,2910.2 9361.29,3023.85 9153.15,3231.98 9153.15,3355.49 9180.59,3397.44 9312.99,3599.85 9312.99,3690.16 9248.15,3755 9148.15,3755 ; KD6.1@10247.07,5429.8 10183.08,5365.81 9969.6,5365.81 8937.19,4333.4 8853.15,4333.4 ; 212,1481.47 212,2229.47 ; 212,2229.47 212,2977.57 ; 212,2977.57 212,3725.17 ; 212,3725.17 212,4473.57 ; 8853.15,4333.4 8853.15,4170 8803.15,4120 8803.15,3999.4 9047.55,3755 9148.15,3755
  Bottom Layer w30: KD1.1@483.27,4406.2 599.87,4522.8 1331.77,4522.8 1386.77,4577.8 2056.77,4577.8 2146.77,4667.8 10372.2,4667.8 10414.3,4625.7 R10.2@10944.3,4625.7 ; v4(501.85,852.8) 560.52,852.8 ; 562.72,855 DD1.1@603.95,876.23 ; R10.2@10950,4620 R10.2@10944.3,4625.7 ; R10.2@10951.85,4625.7 R10.2@10944.3,4625.7
  other v4: 9272.86,4669.08
V_2: DD2.1 KD13.1 KD14.1 KD15.1 KD16.1 KD17.1 KD18.1 KD19.1 KD20.1 KD21.1 KD22.1 KD23.1 R15.2 | length 23493.9
  Top Layer w30: v4(1196.77,810.3) 1201.77,815.3 1201.77,1482.8 ; 1206.77,3727.8 1417.21,3727.8 KD18.1@1487.21,3657.8 ; 1216.77,2242.8 1711.63,2242.8 KD20.1@1792.33,2162.1 ; KD13.1@1309.57,5429.8 1309.57,5405.6 1251.77,5347.8 1216.77,5347.8 1041.77,5172.8 1041.77,4492.8 ; KD17.1@1310.16,4406.2 1223.56,4492.8 1041.77,4492.8 ; KD21.1@1487.22,1395.93 KD21.1@1487.22,1414.1 1418.52,1482.8 1201.77,1482.8 ; KD19.1@1595.48,2910.2 1517.88,2987.8 1201.77,2987.8 ; KD23.1@9754.96,2162.1 10123.15,2530.29 10123.15,2625.54 10161.91,2664.3 10161.91,2665.79 10278.15,2782.03 10278.15,2940 10243.15,2975 10173.15,2975 KD16.1@10109.32,2911.17 ; KD16.1@10109.32,2910.2 KD16.1@10109.32,2911.17 ; 10109.32,3019.73 10109.32,3018.76 ; 10253.15,4720 v4(10150.69,4617.54) 9749.79,4617.54 KD14.1@9538.45,4406.2 9455.73,4323.48 9414.6,4323.48 9359.6,4268.48 9359.6,4148.48 9424.6,4083.48 9524.15,4083.48 9892.78,3714.85 KD15.1@9892.78,3657.8 9892.78,3631.66 9834.6,3573.48 9779.6,3573.48 9719.6,3513.48 9719.6,3408.48 10109.32,3018.76 ; 10256.58,4723.43 10883.15,5350 10933.15,5350 10995.26,5412.11 KD22.1@10995.26,5429.8 ; 1041.77,4492.8 1041.77,3897.8 1201.77,3737.8 1201.77,2987.8 ; 1201.77,1482.8 1201.77,2987.8 ; KD16.1@10109.32,2911.17 10109.32,3018.76
  Bottom Layer w30: DD2.1@189.32,617.83 168.15,596.66 168.15,570 193.15,545 229.6,545 464.89,780.3 591.1,780.3 654.63,810.3 v4(1196.77,810.3) ; KD17.1@1310.16,4406.2 1421.76,4517.8 2086.77,4517.8 2186.77,4617.8 10355.28,4617.8 10398.08,4575 11405,4575 R15.2@11450,4620
V_3: DD3.1 DD4.1 DD5.1 KD24.1 KD25.1 KD26.1 KD27.1 KD28.1 KD29.1 KD30.1 KD31.1 KD32.1 R20.2 | length 24485.2
  Top Layer w8: 251.85,430.7 253.15,432 286.85,465.7
  Top Layer w30: DD3.1@128.87,678.28 86.85,636.27 86.85,585.7 206.25,466.3 ; DD5.1@253.15,390.32 253.15,419.4 ; DD4.1@1743.15,260.32 1743.15,466.3 ; 2141.77,2982.8 2556.34,2982.8 KD30.1@2628.94,2910.2 ; KD31.1@2412.42,1414.1 2328.72,1497.8 2136.77,1497.8 2131.77,1492.8 ; KD29.1@2412.6,3657.8 2337.6,3582.8 2131.77,3582.8 ; KD24.1@2727.56,5429.8 2727.56,5423.6 2651.77,5347.8 2621.77,5347.8 2058.04,4784.08 KD28.1@2058.04,4406.2 2058.04,4372.8 2013.04,4327.8 1946.77,4327.8 1886.77,4267.8 1886.77,4157.8 2131.77,3912.8 2131.77,3582.8 ; KD27.1@10816.96,1414.1 10823.15,1420.29 10823.15,1521.78 10663.15,1681.78 10663.15,3214.93 10479.6,3398.48 10479.6,3503.48 10619.93,3643.81 10640.81,3643.81 KD26.1@10640.81,3657.8 10640.81,3712.34 10394.48,3958.67 10309.42,3958.67 10109.6,4158.48 10109.6,4268.48 10174.6,4333.48 10244.6,4333.48 10286.44,4375.32 KD25.1@10286.44,4406.2 10633.72,4753.48 10946.63,4753.48 11548.69,5355.54 11668.92,5355.54 KD32.1@11743.18,5429.8 ; 206.25,466.3 253.15,419.4 ; 206.25,466.3 253.15,466.3 ; 253.15,419.4 253.15,432 253.15,466.3 ; 253.15,466.3 1743.15,466.3 ; 1743.15,466.3 1743.15,744.83 2131.77,1133.45 2131.77,1492.8 ; 2131.77,1492.8 2131.77,3582.8
  Bottom Layer w30: KD28.1@2058.04,4406.2 2219.64,4567.8 10336.77,4567.8 10376.77,4527.8 v4(10401.77,4527.8) 11857.8,4527.8 R20.2@11950,4620
V_4: DD6.1 DD7.1 KD33.1 KD34.1 KD35.1 KD36.1 KD37.1 KD38.1 KD39.1 KD40.1 KD41.1 KD42.1 KD43.1 R25.2 | length 22653.6
  Top Layer w30: KD37.1@3021.85,2165.7 3316.85,2460.7 3316.85,2550.7 3202.88,2664.67 3202.88,2773.92 3261.77,2832.8 3321.77,2832.8 3377.01,2888.05 KD36.1@3377.01,2910.2 3377.01,3022.56 2981.77,3417.8 2981.77,3522.8 3036.77,3577.8 3101.77,3577.8 3160.48,3636.52 KD35.1@3160.48,3657.8 3160.48,3682.67 3112.5,3730.65 3053.92,3730.65 2636.77,4147.8 2636.77,4277.8 2686.77,4327.8 2727.75,4327.8 KD34.1@2806.15,4406.2 2806.15,4797.19 3361.77,5352.8 3398.56,5352.8 KD33.1@3475.56,5429.8 ; KD37.1@3022.65,2162.1 3022.65,2138.69 2966.77,2082.8 2911.77,2082.8 2851.77,2022.8 2851.77,1912.8 3337.62,1426.95 KD38.1@3337.62,1414.1 3337.62,1315.53 3392.26,1260.9 3392.26,1182.47 3377.57,1160.02 3358.12,1130.28 ; DD6.1@3243.15,160.32 3243.15,258 3270.15,285 4707.6,285 4733.15,259.45 DD7.1@4733.15,100.42 ; 3330.11,286 3355.55,311.45 ; 3357.11,288.11 3357.11,309.89 ; 3357.11,1128.74 3357.11,313 ; 3381,286 3357.11,309.89 ; v4(11051.77,4477.8) 11051.77,4409.09 11221.77,4239.09 ; KD42.1@11123.07,2162.1 KD42.1@11123.07,2152.93 ; KD39.1@11388.88,4406.2 11221.77,4239.09 ; KD40.1@11565.97,3637.82 KD40.1@11565.97,3657.8 ; KD43.1@11742.16,1414.1 11669.8,1486.47 11358.1,1486.47 10966.77,1877.8 10966.77,2012.8 11106.89,2152.93 KD42.1@11123.07,2152.93 ; v4(12540,4490) v4(12540,4645.59) ; 3355.55,311.45 3357.11,309.89 ; 3355.55,311.45 3357.11,313 ; 3357.11,309.89 3357.11,313 ; KD42.1@11123.07,2152.93 11061.77,2214.23 11061.77,2671.71 KD41.1@11300.26,2910.2 11300.26,3392.09 KD40.1@11565.97,3657.8 ; 11221.77,4239.09 11221.77,4147.8 11565.97,3803.6 KD40.1@11565.97,3657.8
  Bottom Layer w12: R25.2@12523.5,4629.09 v4(12540,4645.59)
  Bottom Layer w30: KD34.1@2806.15,4406.2 2917.75,4517.8 3161.77,4517.8 ; 3121.77,4517.8 3161.77,4517.8 ; v4(11051.77,4477.8) 10361.77,4477.8 10321.77,4517.8 3161.77,4517.8 ; KD39.1@11396.95,4406.2 KD39.1@11388.88,4406.2 11467.28,4327.8 12339.8,4327.8 12502,4490 v4(12540,4490)
V_5: DD8.1 DD9.1 KD44.1 KD45.1 KD46.1 KD47.1 KD48.1 KD49.1 KD50.1 KD51.1 KD52.1 R30.2 | length 21349.7
  Top Layer w20: KD49.1@12766.77,4402.8 KD49.1@12766.77,4406.2
  Top Layer w30: KD44.1@4217.8,5429.8 KD44.1@4223.56,5429.8 ; KD44.1@4219.6,5418.48 4149.6,5348.48 4099.6,5348.48 3554.14,4803.03 KD45.1@3554.14,4406.2 3391.77,4243.83 3391.77,4142.8 3711.77,3822.8 3805.35,3822.8 3908.51,3719.64 3908.51,3664.55 3746.77,3502.8 3746.77,3402.8 4125.04,3024.53 KD52.1@4125.04,2910.2 4042.64,2827.8 4021.77,2827.8 3770.71,2576.75 KD47.1@3770.71,2162.1 3691.41,2082.8 3666.77,2082.8 3601.77,2017.8 3601.77,1907.8 3811.77,1697.8 4029.2,1697.8 4487,1240 4487,987 5119,355 6133.15,355 6243.15,245 ; DD8.1@6243.15,100 6243.15,245 ; DD9.1@7733.15,125.49 7733.15,200 ; 10848.08,75 11011.77,75 ; KD49.1@12766.77,4402.8 12964.6,4204.97 12964.6,3963.48 12766.77,3765.65 KD50.1@12766.77,3657.8 12766.77,3641.32 12959.6,3448.48 12959.6,3017.6 12842,2900 12842,1489.33 KD51.1@12766.78,1414.1 KD51.1@12766.78,1400 ; KD49.1@12766.77,4406.2 12766.77,4471.95 12947.62,4652.8 v4(13026.77,4652.8) 13026.77,5169.95 KD48.1@12766.92,5429.8 ; KD51.1@12773.83,1407.05 KD51.1@12766.78,1400 ; KD49.1@12776.54,4396.43 KD49.1@12776.54,4401.43 ; v4(12782,75) 11011.77,75 ; v4(12782,335) 12782,878.04 12954.6,1050.64 12954.6,1198.48 12766.78,1386.31 KD51.1@12766.78,1400 ; 6243.15,245 6259.67,228.48 7704.67,228.48 7733.15,200 ; 7733.15,200 10047,200 10190.48,343.48 10526.77,343.48 10795.25,75 11011.77,75
  Bottom Layer w20: R30.2@13021.77,4616.77 v4@13021.77,4647.8
  Bottom Layer w30: v4(12782,75) v4(12782,335)
V_6: DD10.1 DD11.1 KD53.1 KD54.1 KD55.1 KD56.1 KD57.1 KD58.1 KD59.1 KD60.1 KD61.1 KD62.1 R35.2 | length 21301.3
  Top Layer w30: KD53.1@4971.57,5429.8 4891.76,5350 4867,5350 4302.18,4785.17 KD58.1@4302.18,4406.2 4141.77,4245.8 4141.77,4152.8 4331.77,3962.8 4396.77,3962.8 4656.51,3703.06 KD59.1@4656.51,3657.8 4491.77,3493.06 4491.77,3402.8 4873.09,3021.48 KD60.1@4873.09,2910.2 4869.17,2910.2 4518.73,2559.76 KD61.1@4518.73,2162.1 4356.77,2000.14 4356.77,1912.8 4661.77,1607.8 4661.77,1055.23 5219.2,497.8 9313.15,497.8 ; DD10.1@9313.15,280.32 9313.15,497.8 ; KD62.1@13514.8,5429.8 13441.54,5356.54 13407.66,5356.54 13350.46,5299.34 13350.46,5157.63 13514.84,4993.24 KD54.1@13514.84,4406.2 13437.12,4328.48 13399.6,4328.48 13339.6,4268.48 13339.6,4163.48 13514.84,3988.24 KD55.1@13514.84,3657.8 13514.84,3608.72 13479.6,3573.48 13414.6,3573.48 13349.6,3508.48 13349.6,3403.48 13514.81,3238.27 KD56.1@13514.81,2162.1 13514.81,2128.69 13464.6,2078.48 13409.6,2078.48 13349.6,2018.48 13349.6,1903.48 13514.81,1738.27 KD57.1@13514.81,1414.1 13439.19,1338.48 13409.6,1338.48 13339.6,1268.48 13339.6,1163.48 13527,976.08 13527,300.51 v4(13521.49,295) ; v4@13521.49,125 10919.62,125 10803.15,241.47 DD11.1@10803.15,280.32 10803.15,441.32 10746.66,497.8 9313.15,497.8
  Bottom Layer w30: R35.2@13515,4620 v4(13515,4645.59) ; v4(13521.49,123.48) v4(13521.49,295)
V_7: DD12.1 DD13.1 KD63.1 KD64.1 KD65.1 KD66.1 KD67.1 KD68.1 KD69.1 KD70.1 KD71.1 KD72.1 R40.2 | length 21311.3
  Top Layer w30: KD64.1@5050.17,4406.2 5123.91,4479.95 5223.15,4479.95 ; KD72.1@5266.76,2162.1 5266.76,2184.61 5313.15,2231 5433,2231 ; 5424.06,3300.15 5424.06,3372.44 ; 5428.03,2230.12 5453.15,2205 ; 5452.15,2231 5433,2231 ; KD63.1@6113.57,5429.8 6113.57,5389.61 6056.77,5332.8 5996.77,5332.8 5223.15,4559.19 5223.15,4479.95 ; DD12.1@12597.15,340.11 12597.15,203.48 ; DD13.1@13780.15,280.32 13780.15,238.48 13745.15,203.48 13693.29,203.48 ; KD66.1@14262.99,5429.8 14176.67,5343.48 14149.6,5343.48 14098.13,5292.02 14098.13,5154.95 14199.6,5053.48 14199.6,4738.48 14262.87,4675.21 KD67.1@14262.87,4406.2 14180.15,4323.48 14164.6,4323.48 14094.6,4253.48 14094.6,4153.48 14262.87,3985.21 KD68.1@14262.87,3657.8 14262.87,3631.75 14209.6,3578.48 14154.6,3578.48 14099.6,3523.48 14099.6,3393.48 14192,3301.08 14192,1510 14262.85,1439.15 KD69.1@14262.85,1414.1 14262.85,1381.73 14214.6,1333.48 14109.6,1333.48 13693.29,917.18 13693.29,203.48 ; 5223.15,4479.95 5223.15,4376.15 5104.8,4257.8 5104.8,4174.57 5073.15,4126.18 5069.65,4120.84 5069.65,4062 5404.58,3727.08 KD70.1@5404.58,3657.8 5466.77,3720 5548.15,3720 5573.15,3695 5573.15,3625 5459.21,3511.06 5459.21,3426.17 5424.06,3372.44 ; 5424.06,3372.44 5424.06,3112.87 5621.12,2915.81 5621.12,2947.97 5668.15,2995 5753.97,2995 5783.15,2965.81 5783.15,2826.15 5684.22,2727.22 5684.22,2691.51 5640.6,2624.84 5640.6,2536.6 5453.15,2349.15 5453.15,2251.15 ; 5433,2231 5453.15,2251.15 ; 5453.15,2205 5453.15,2251.15 ; 5453.15,2205 5453.15,2144 5321.39,2012.24 5321.39,1930.47 5288.15,1879.65 5286.24,1876.74 5286.24,1814 5326.24,1774 5568.71,1774 5769.22,1573.48 6114.67,1573.48 6152.59,1535.56 KD65.1@6152.59,1414.1 6152.59,1407.12 6218.15,1341.56 6218.15,1180 6173.15,1135 6173.15,1071.4 6691.75,552.8 10798.97,552.8 11033.97,317.8 11299.2,317.8 11413.52,203.48 12597.15,203.48 ; 12597.15,203.48 13693.29,203.48
  Bottom Layer w20: R40.2@14210,4620 v4@14239.57,4620
  other v4: 14241.77,4617.8
V_8: DD14.1 DD15.1 KD73.1 KD74.1 KD75.1 KD76.1 KD77.1 KD78.1 KD79.1 KD80.1 KD81.1 LED1.1 LED2.1 R45.2 | length 24307.7
  Top Layer w20: LED2.1@15628.5,5253.27 15646.85,5234.91 15646.85,5073.48 15646.85,5060.53 ; v4(16085,5073.48) 16085,5173 16138.5,5226.5 LED1.1@16138.5,5253.27
  Top Layer w30: KD75.1@6861.23,5429.8 6861.23,5380.11 6829.6,5348.48 6721.63,5348.48 5798.2,4425.05 KD76.1@5798.2,4406.2 5798.2,4377.08 5744.6,4323.48 5679.6,4323.48 5624.6,4268.48 5624.6,4153.48 5777.73,4000.35 5932.73,4000.35 6152.57,3780.51 KD77.1@6152.57,3657.8 6152.57,3631.45 6104.6,3583.48 6054.6,3583.48 5984.6,3513.48 5984.6,3393.48 6359.6,3018.48 6359.6,2868.48 6319.6,2828.48 6264.6,2828.48 6014.79,2578.67 KD79.1@6014.79,2162.1 6014.79,2138.67 5951.32,2075.2 5851.32,2075.2 5774.6,1998.48 5774.6,1703.48 5824.6,1653.48 6221.28,1653.48 6399.6,1475.16 6399.6,923.87 6714.98,608.48 7449.6,608.48 ; 7464.73,608.48 7449.6,608.48 ; v4@11168.12,573.88 11133.52,608.48 7449.6,608.48 ; KD81.1@15276.65,2174.11 15276.65,2603.5 15346.77,2673.62 15346.77,2757.8 15286.03,2818.54 KD80.1@15286.03,2910.2 15286.03,3362.17 15339.98,3416.13 15339.98,3497.98 15462,3620 15462,3687.8 15417,3732.8 15306.77,3732.8 ; KD74.1@15285.67,3657.8 15306.77,3678.9 15306.77,3732.8 ; KD73.1@15286.45,4406.2 15286.45,4361.09 15316.85,4330.7 15368.29,4330.7 ; DD14.1@15296.48,425.32 15296.48,386 15307.48,375 16776.48,375 16793.48,392 DD15.1@16793.48,421.32 ; 15646.85,5070.7 15646.85,4837.55 15587,4777.7 v4(15587,4700.15) 15587,4453.19 15464.51,4330.7 15368.29,4330.7 ; 15646.85,5073.48 v4(15718.5,5073.48) ; 15306.77,3732.8 15306.77,4127.8 15368.29,4189.33 15368.29,4330.7
  Bottom Layer w30: v4(11167.73,573.48) 13426.09,573.48 13726.09,273.48 15334.6,273.48 15393.15,332.03 15393.15,1179.8 15358.15,1214.8 15358.15,1630 15318.15,1670 15097,1670 15008.15,1758.85 15008.15,2205.61 15047.54,2245 15205.77,2245 KD81.1@15276.65,2174.11 ; R45.2@15587,4670 v4(15587,4700.15) ; v4(15718.5,5073.48) v4(16085,5073.48)
  other v4: 15392.48,380
V_9: DD16.1 KD82.1 KD83.1 KD84.1 KD85.1 KD86.1 KD87.1 KD88.1 KD89.1 KD90.1 KD91.1 LED3.1 R50.2 | length 21476.1
  Top Layer w20: LED3.1@16668.5,5253.27 16668.5,5246.01 16688.01,5226.5 v4(16697,5226.5)
  Top Layer w30: KD90.1@6762.82,2162.1 6762.82,2987.8 6776.85,2987.8 ; KD88.1@6900.64,3657.8 6810.64,3747.8 6616.77,3747.8 ; KD89.1@7117.18,2910.2 7039.58,2987.8 6776.85,2987.8 ; v4(7829.15,5333) 7706.12,5333 KD82.1@7609.31,5429.8 7609.31,5405.35 7551.77,5347.8 7487.84,5347.8 KD87.1@6546.24,4406.2 6386.77,4246.73 6386.77,4137.8 6616.77,3907.8 6616.77,3747.8 ; KD91.1@15650.67,1414.1 15650.67,1759.56 15869.6,1978.48 15869.6,2028.48 15934.6,2093.48 15960.98,2093.48 16033.15,2165.65 16093.15,2105.65 16158.8,2105.65 16193.15,2140 16193.15,2345.85 15880,2659 15880,2755.5 KD85.1@16034.7,2910.2 16034.7,3251.3 15875,3411 15875,3498.28 KD84.1@16034.52,3657.8 16034.52,3996.48 15878,4153 15878,4249.5 KD83.1@16034.7,4406.2 ; KD83.1@16038.15,4409.65 KD83.1@16034.7,4406.2 ; v4(16147,5163.48) 16147,4710 ; v4(16207,4710) 16147,4710 ; 6616.77,3747.8 6616.77,3147.89 6776.85,2987.8 ; KD83.1@16034.7,4406.2 16034.7,4586.78 16147,4699.07 16147,4710
  Bottom Layer w30: v4(7829.15,5333) 8386.15,5333 8423.15,5296 9188.9,5296 9222.9,5330 11837,5330 12002,5165 12492,5165 12657,5330 14287.15,5330 14372.35,5244.8 16117.2,5244.8 16147,5215 v4(16147,5163.48) ; KD91.1@15650.67,1414.1 15766.57,1530 16867,1530 17717,680 17717,645 17687,615 17662.43,615 DD16.1@17636,641.44 ; 16138.5,5226.5 v4(16697,5226.5) ; R50.2@16209.6,4677 v4@16209.6,4706
V_10: DD17.1 KD92.1 KD93.1 KD94.1 KD95.1 KD96.1 KD97.1 KD98.1 KD99.1 KD100.1 KD101.1 LED4.1 R55.2 | length 19830.3
  Top Layer w20: 16506.77,3732.8 16711.77,3732.8 16781.75,3662.82 KD94.1@16781.75,3657.8 ; 16507.56,2237.1 16712.56,2237.1 16781.33,2168.33 16782.54,2167.12 KD100.1@16782.54,2162.1 ; 16507.77,2985.2 16712.77,2985.2 16782.75,2915.22 KD95.1@16782.75,2910.2 ; 16867,5210 17197,5210 17208.5,5221.5 LED4.1@17208.5,5243.48
  Top Layer w30: KD99.1@7510.85,2162.1 7510.85,2561.89 7865.21,2916.25 7865.21,3014.36 7486.77,3392.8 7486.77,3495.89 KD97.1@7648.68,3657.8 7648.68,3669.78 7577,3741.47 7543.1,3741.47 7131.77,4152.8 7131.77,4243.66 KD96.1@7294.31,4406.2 7294.31,4413.78 8234.02,5353.48 8287.84,5353.48 8357.35,5422.98 8425.35,5354.98 8483.92,5354.98 v4(8539.92,5410.98) ; KD100.1@16778.82,2165.82 16781.33,2168.33 KD100.1@16782.54,2169.54 ; KD101.1@16782.72,1414.1 16506.77,1690.05 16506.77,3732.8 16506.77,4130.44 KD93.1@16782.53,4406.2 16788.15,4411.83 16788.15,4605.85 16867,4684.7 ; v4(16867,5373.48) 16867,5210 16867,4684.7 ; v4@16883.3,4701 16867,4684.7 ; DD17.1@17575.87,647.72 17547.31,676.28 17547.31,694.16 v4(17582.87,729.72)
  Bottom Layer w30: v4@8539.92,5412.3 9106.2,5412.3 9238.9,5545 14349.8,5545 14521.31,5373.48 v4(16867,5373.48) ; KD101.1@16782.72,1414.1 16861.82,1335 16977.6,1335 v4(17582.87,729.72)
  other v4: 16887,4710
